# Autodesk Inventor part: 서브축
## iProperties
Created: 2011-12
Part Number: 서브축
Document SubType Name: Modeling
Designer: 석형태
Density: 1 g/cm^3
Material: 기본값
Mass: 18.2127 g
Surface Area: 62.0354 cm^2
Volume: 18.2127 cm^3
Author: 석형태
